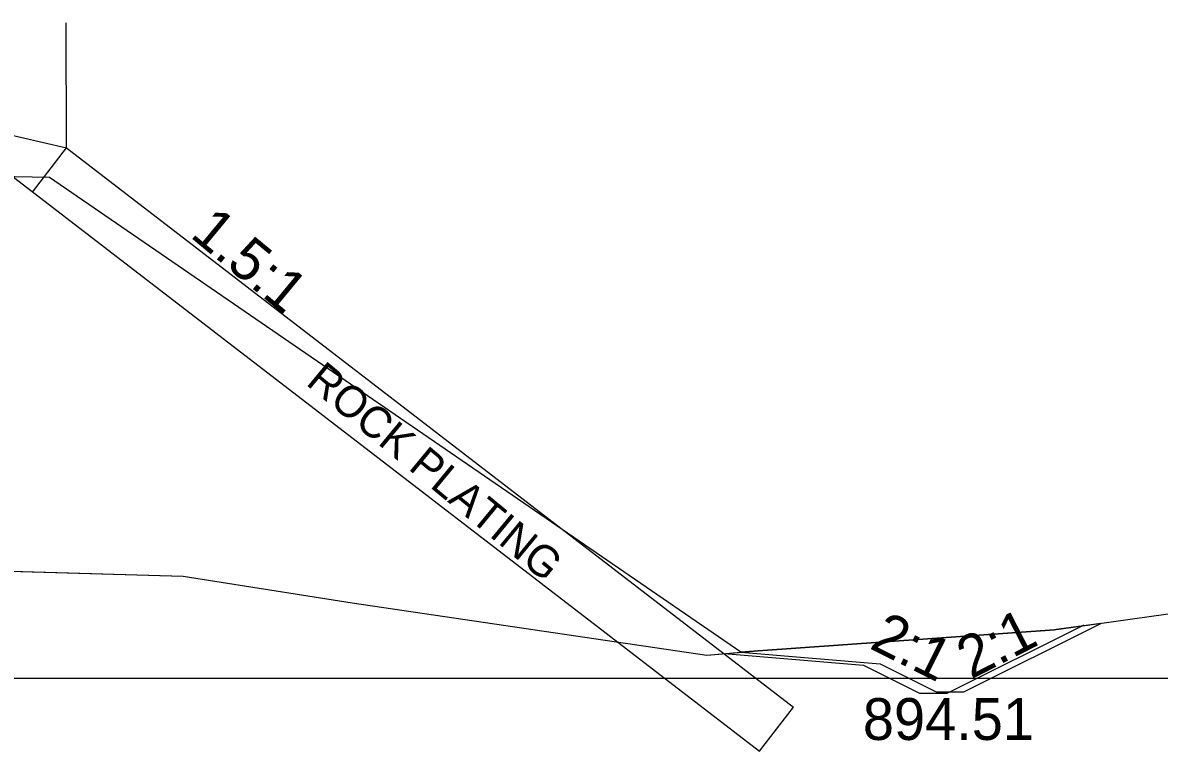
# Model space of a CAD drawing. Extents: x -26 to 1640245, y -10 to 842531.
# Drawn here: x 179.26 to 220, y 1497.38 to 1523.49 of the extents above; entities that cross this region are included whole.
import ezdxf

# ---------------------------------------------------------------- set-up
doc = ezdxf.new("R2010")
doc.units = 0
for name, color, linetype in [('Exist Cross Section Cell', 7, 'Continuous'), ('Exist XS Ground Line', 7, 'Continuous'), ('Prop CMT Slope Grass', 7, 'Continuous'), ('Prop XS Class B Stone Ditch Liner', 7, 'Continuous'), ('Prop XS Ditch Standard Text', 7, 'Continuous'), ('Prop XS Side Slope Text', 7, 'Continuous'), ('Scratch_Level_2', 7, 'Continuous'), ('Scratch_Level_3', 7, 'Continuous'), ('Scratch_Level_4', 7, 'Continuous'), ('Scratch_Level_5', 7, 'Continuous')]:
    doc.layers.add(name, color=color, linetype=linetype)

msp = doc.modelspace()

# ---------------------------------------------------------------- linework, layer by layer
at = {"layer": 'Exist Cross Section Cell'}
msp.add_line((150, 1500), (300, 1500), dxfattribs=at)
at = {"layer": 'Exist XS Ground Line'}
for p, q in [((176.355, 1503.904), (185.009, 1503.652)), ((185.009, 1503.652), (191.072, 1502.702)), ((191.072, 1502.702), (203.782, 1500.824)), ((216.407, 1501.752), (223.636, 1502.769)), ((205.628, 1500.979), (216.248, 1501.731)), ((216.248, 1501.731), (216.306, 1501.737)), ((216.306, 1501.737), (216.407, 1501.752)), ((203.782, 1500.824), (205.628, 1500.979))]:
    msp.add_line(p, q, dxfattribs=at)
at = {"layer": 'Prop CMT Slope Grass'}
for p, q in [((177.157, 1519.311), (205.671, 1497.377)), ((213, 1499.511), (217.902, 1501.962)), ((205, 1500.926), (210, 1500.511)), ((210, 1500.511), (212, 1499.511)), ((212, 1499.511), (213, 1499.511))]:
    msp.add_line(p, q, dxfattribs=at)
at = {"layer": 'Prop XS Class B Stone Ditch Liner'}
for p, q in [((177.904, 1519.684), (180.833, 1519.007)), ((179.613, 1517.422), (180.833, 1519.007)), ((180.833, 1519.007), (206.891, 1498.962)), ((205.671, 1497.377), (206.891, 1498.962))]:
    msp.add_line(p, q, dxfattribs=at)
at = {"layer": 'Scratch_Level_2'}
for p, q in [((213, 1499.511), (217.902, 1501.962)), ((217.902, 1501.962), (216.407, 1501.752)), ((205, 1500.926), (210, 1500.511)), ((210, 1500.511), (212, 1499.511)), ((212, 1499.511), (213, 1499.511))]:
    msp.add_line(p, q, dxfattribs=at)
msp.add_lwpolyline([(216.407, 1501.752), (216.306, 1501.737), (216.248, 1501.731), (205.628, 1500.979), (205, 1500.926)], dxfattribs=at)
at = {"layer": 'Scratch_Level_3'}
for p, q in [((180.224, 1517.942), (175.436, 1518.037)), ((205, 1500.926), (180.224, 1517.942))]:
    msp.add_line(p, q, dxfattribs=at)
msp.add_lwpolyline([(176.355, 1503.904), (185.009, 1503.652), (191.072, 1502.702), (203.782, 1500.824), (205, 1500.926)], dxfattribs=at)
at = {"layer": 'Scratch_Level_4'}
for p, q in [((212.401, 1499.462), (217.304, 1501.913)), ((204.401, 1500.877), (209.401, 1500.462)), ((209.401, 1500.462), (211.401, 1499.462)), ((211.401, 1499.462), (212.401, 1499.462))]:
    msp.add_line(p, q, dxfattribs=at)
at = {"layer": 'Scratch_Level_5'}
msp.add_line((180.833, 1519.014), (180.812, 1523.49), dxfattribs=at)

# ---------------------------------------------------------------- texts
at = {"layer": 'Prop XS Ditch Standard Text'}
msp.add_text('894.51', height=1.5, dxfattribs=at).set_placement((209.376, 1497.782))
at = {"layer": 'Prop XS Side Slope Text'}
for s, height, rotation, p in [('1.5:1', 1.5, 320.4211, (185.218, 1515.837)), ('ROCK PLATING', 1.125, 320.4211, (189.373, 1510.542)), ('2:1', 1.5, 333.4346, (209.569, 1501.088)), ('2:1', 1.5, 27.1286, (213.255, 1499.946))]:
    msp.add_text(s, height=height, rotation=rotation, dxfattribs=at).set_placement(p)

doc.saveas('drawing.dxf')
